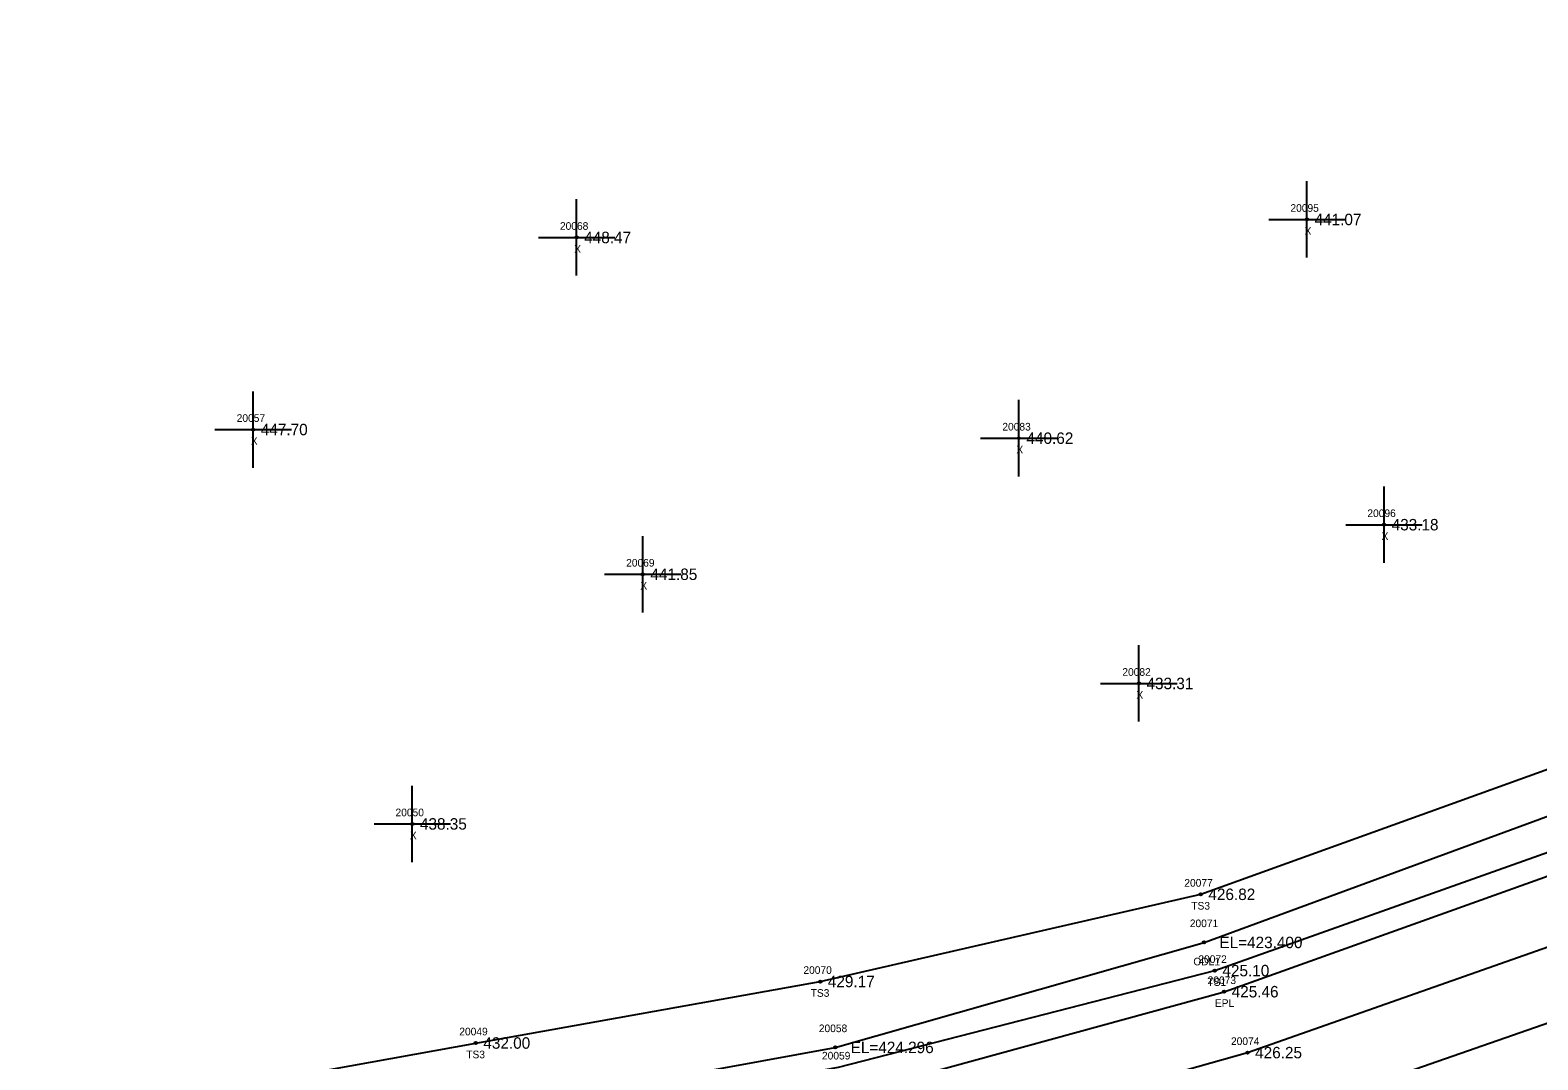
# Model space of a CAD drawing. Extents: x 2116373 to 2118139, y 979529 to 981026.
# Drawn here: x 2116558 to 2116755.3, y 979693.5 to 979828.4 of the extents above; entities that cross this region are included whole.
import ezdxf

# ---------------------------------------------------------------- set-up
doc = ezdxf.new("R2010")
doc.units = 0
for name, color, linetype in [('RD_DTM_BkLn1', 7, 'Continuous'), ('RD_DTM_BkLn2', 7, 'Continuous'), ('RD_DTM_BkLn_txCode', 7, 'Continuous'), ('RD_EX_H2O', 7, 'Continuous'), ('RD_EX_H2O_txCode', 7, 'Continuous'), ('RD_EX_Misc', 7, 'Continuous'), ('RD_EX_Misc_txCode', 7, 'Continuous'), ('RD_EX_Road', 7, 'Continuous'), ('RD_EX_Road_txCode', 7, 'Continuous'), ('RD_EX_TX_H2O_ELEV', 7, 'Continuous'), ('RD_EX_TX_Misc_ELEV', 7, 'Continuous'), ('RD_EX_TX_Road_ELEV', 7, 'Continuous'), ('RD_HC_Survey_ELEV', 7, 'Continuous'), ('RD_HC_Survey_txCode', 7, 'Continuous'), ('RD_SMD_Locator', 7, 'Continuous')]:
    doc.layers.add(name, color=color, linetype=linetype)

msp = doc.modelspace()

# ---------------------------------------------------------------- linework, layer by layer
at = {"layer": 'RD_DTM_BkLn1'}
msp.add_lwpolyline([(2116414.21, 979630.19), (2116468.62, 979643.23), (2116521.45, 979653.6), (2116618.87, 979670.38), (2116668.4, 979680.7), (2116717.3, 979694.48), (2116764.56, 979711.13), (2116810.15, 979729.38), (2116856.49, 979749.81), (2116900.74, 979773.15), (2116944.03, 979798.93), (2116982.75, 979824.6), (2117026.56, 979857.02), (2117064.34, 979888.81), (2117101.78, 979922.69), (2117176.3, 979989.4), (2117250.99, 980056.19), (2117326.56, 980126.36)], dxfattribs=at)
at = {"layer": 'RD_DTM_BkLn2'}
for points in [[(2116410.78, 979641.79), (2116465.45, 979654.97), (2116518.83, 979664.89), (2116614.96, 979683.75), (2116663.75, 979692.58), (2116713.02, 979705.22), (2116760.07, 979721.97), (2116804.88, 979741.47), (2116850.79, 979761.38), (2116894.83, 979783.88), (2116937.98, 979807.44), (2116977.39, 979833.6), (2117020.56, 979865.29), (2117056.86, 979896.38), (2117094.29, 979932.2), (2117168.14, 979997.38), (2117238.71, 980069.61), (2117312.33, 980134.21), (2117318.43, 980135.16)], [(2116408.48, 979653.74), (2116461.38, 979665.42), (2116520.7, 979678.48), (2116616.28, 979695.74), (2116661.37, 979703.79), (2116711.18, 979715.21), (2116757.77, 979732.03), (2116802.04, 979749.54), (2116847.76, 979769.63), (2116889.13, 979795.82), (2116931.32, 979820.72), (2116972.01, 979847.71), (2117009.67, 979877.33), (2117051.05, 979910.18), (2117086.71, 979942.74), (2117161.4, 980003.96), (2117222.13, 980080.24), (2117265.44, 980120.03)]]:
    msp.add_lwpolyline(points, dxfattribs=at)
at = {"layer": 'RD_EX_H2O'}
msp.add_lwpolyline([(2116411.09, 979644.42), (2116463.93, 979657.73), (2116517.88, 979668.38), (2116615.09, 979686.35), (2116663.35, 979695.16), (2116711.62, 979708.91), (2116758.49, 979726.13), (2116778.25, 979736.27), (2116803.5, 979744.47), (2116849.89, 979764.23), (2116894.14, 979786.32), (2116936.31, 979809.39), (2116976.21, 979834.9), (2117018.41, 979867.86), (2117054.24, 979898.91), (2117093.35, 979934.14), (2117166.11, 979999.69), (2117224.07, 980077.92), (2117265.44, 980120.03)], dxfattribs=at)
at = {"layer": 'RD_EX_Misc'}
for p, q in [((2116725.08, 979798.58), (2116725.08, 979808.58)), ((2116629.48, 979796.22), (2116629.48, 979806.22)), ((2116720.08, 979803.58), (2116730.08, 979803.58)), ((2116624.48, 979801.22), (2116634.48, 979801.22)), ((2116587.15, 979771.07), (2116587.15, 979781.07)), ((2116687.37, 979769.94), (2116687.37, 979779.94)), ((2116582.15, 979776.07), (2116592.15, 979776.07)), ((2116682.37, 979774.94), (2116692.37, 979774.94)), ((2116735.17, 979758.61), (2116735.17, 979768.61)), ((2116638.15, 979752.12), (2116638.15, 979762.12)), ((2116730.17, 979763.61), (2116740.17, 979763.61)), ((2116633.15, 979757.12), (2116643.15, 979757.12)), ((2116703.08, 979737.82), (2116703.08, 979747.82)), ((2116698.08, 979742.82), (2116708.08, 979742.82)), ((2116607.98, 979719.43), (2116607.98, 979729.43)), ((2116602.98, 979724.43), (2116612.98, 979724.43))]:
    msp.add_line(p, q, dxfattribs=at)
at = {"layer": 'RD_EX_Road'}
for points in [[(2116412.2, 979638.84), (2116468.17, 979651.36), (2116519.2, 979662.5), (2116617.24, 979678.85), (2116665.51, 979689.1), (2116714.23, 979702.46), (2116761.42, 979719.35), (2116806.99, 979737.42), (2116852.23, 979758.11), (2116896.57, 979780.91), (2116939.1, 979805.52), (2116978.46, 979832.1), (2117021.29, 979863.87), (2117058.15, 979895.61), (2117096.06, 979930.47), (2117170.14, 979995.71), (2117244.91, 980062.82), (2117320.63, 980133.49), (2117326.56, 980126.36)], [(2116416.36, 979621.21), (2116470.51, 979634.11), (2116523.97, 979644.68), (2116620.55, 979661.21), (2116670.7, 979671.96), (2116720.65, 979685.84), (2116767.66, 979702.22), (2116814.07, 979721.02), (2116860.35, 979742.3), (2116904.9, 979765.18), (2116949.06, 979791.19), (2116988.09, 979817.15), (2117031.94, 979849.78), (2117069.79, 979881.53), (2117108.89, 979916.38), (2117182.06, 979982.67), (2117257.56, 980049.29), (2117334.73, 980117.38), (2117326.56, 980126.36)]]:
    msp.add_lwpolyline(points, dxfattribs=at)
at = {"layer": 'RD_SMD_Locator'}
for centre in [(2116725.08, 979803.58), (2116629.48, 979801.22), (2116587.15, 979776.07), (2116687.37, 979774.94), (2116735.17, 979763.61), (2116638.15, 979757.12), (2116703.08, 979742.82), (2116607.98, 979724.43), (2116711.18, 979715.21), (2116711.62, 979708.91), (2116713.02, 979705.22), (2116661.37, 979703.79), (2116714.23, 979702.46), (2116616.28, 979695.74), (2116663.35, 979695.16), (2116717.3, 979694.48)]:
    msp.add_circle(centre, 0.15, dxfattribs=at)

# ---------------------------------------------------------------- texts
at = {"layer": 'RD_DTM_BkLn_txCode'}
for s, p in [('20077', (2116709.03, 979716.21)), ('TS3', (2116709.94, 979713.21)), ('20072', (2116710.87, 979706.22)), ('20070', (2116659.17, 979704.79)), ('TS3', (2116660.12, 979701.79)), ('TS1', (2116712.06, 979703.22)), ('20049', (2116614.13, 979696.74)), ('TS3', (2116615.04, 979693.74)), ('20059', (2116661.6, 979693.58))]:
    msp.add_text(s, height=1, dxfattribs=at).set_placement(p)
at = {"layer": 'RD_EX_H2O_txCode'}
for s, p in [('20071', (2116709.75, 979710.91)), ('ODL1', (2116710.21, 979705.91)), ('20058', (2116661.19, 979697.16))]:
    msp.add_text(s, height=1, dxfattribs=at).set_placement(p)
at = {"layer": 'RD_EX_Misc_txCode'}
for s, p in [('20095', (2116722.92, 979804.58)), ('20068', (2116627.3, 979802.22)), ('X', (2116724.77, 979801.58)), ('X', (2116629.17, 979799.22)), ('20057', (2116584.99, 979777.07)), ('20083', (2116685.21, 979775.94)), ('X', (2116586.84, 979774.07)), ('X', (2116687.05, 979772.94)), ('20096', (2116732.99, 979764.61)), ('X', (2116734.85, 979761.61)), ('20069', (2116635.97, 979758.12)), ('X', (2116637.83, 979755.12)), ('20082', (2116700.92, 979743.82)), ('X', (2116702.76, 979740.82)), ('20050', (2116605.78, 979725.43)), ('X', (2116607.66, 979722.43))]:
    msp.add_text(s, height=1, dxfattribs=at).set_placement(p)
at = {"layer": 'RD_EX_Road_txCode'}
for s, p in [('20073', (2116712.08, 979703.46)), ('EPL', (2116713.03, 979700.46))]:
    msp.add_text(s, height=1, dxfattribs=at).set_placement(p)
at = {"layer": 'RD_EX_TX_H2O_ELEV'}
for s, p in [('EL=423.400', (2116713.62, 979708.16)), ('EL=424.296', (2116665.35, 979694.41))]:
    msp.add_text(s, height=1.5, dxfattribs=at).set_placement(p)
at = {"layer": 'RD_EX_TX_Misc_ELEV'}
for s, p in [('441.07', (2116726.08, 979802.83)), ('448.47', (2116630.48, 979800.47)), ('447.70', (2116588.15, 979775.32)), ('440.62', (2116688.37, 979774.19)), ('433.18', (2116736.17, 979762.86)), ('441.85', (2116639.15, 979756.37)), ('433.31', (2116704.08, 979742.07)), ('438.35', (2116608.98, 979723.68)), ('426.82', (2116712.18, 979714.46)), ('425.10', (2116714.02, 979704.47)), ('429.17', (2116662.37, 979703.04)), ('432.00', (2116617.28, 979694.99))]:
    msp.add_text(s, height=1.5, dxfattribs=at).set_placement(p)
at = {"layer": 'RD_EX_TX_Road_ELEV'}
msp.add_text('425.46', height=1.5, dxfattribs=at).set_placement((2116715.23, 979701.71))
at = {"layer": 'RD_HC_Survey_ELEV'}
msp.add_text('426.25', height=1.5, dxfattribs=at).set_placement((2116718.3, 979693.73))
at = {"layer": 'RD_HC_Survey_txCode'}
msp.add_text('20074', height=1, dxfattribs=at).set_placement((2116715.14, 979695.48))

doc.saveas('drawing.dxf')
